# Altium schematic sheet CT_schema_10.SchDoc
size 209 x 185 mm
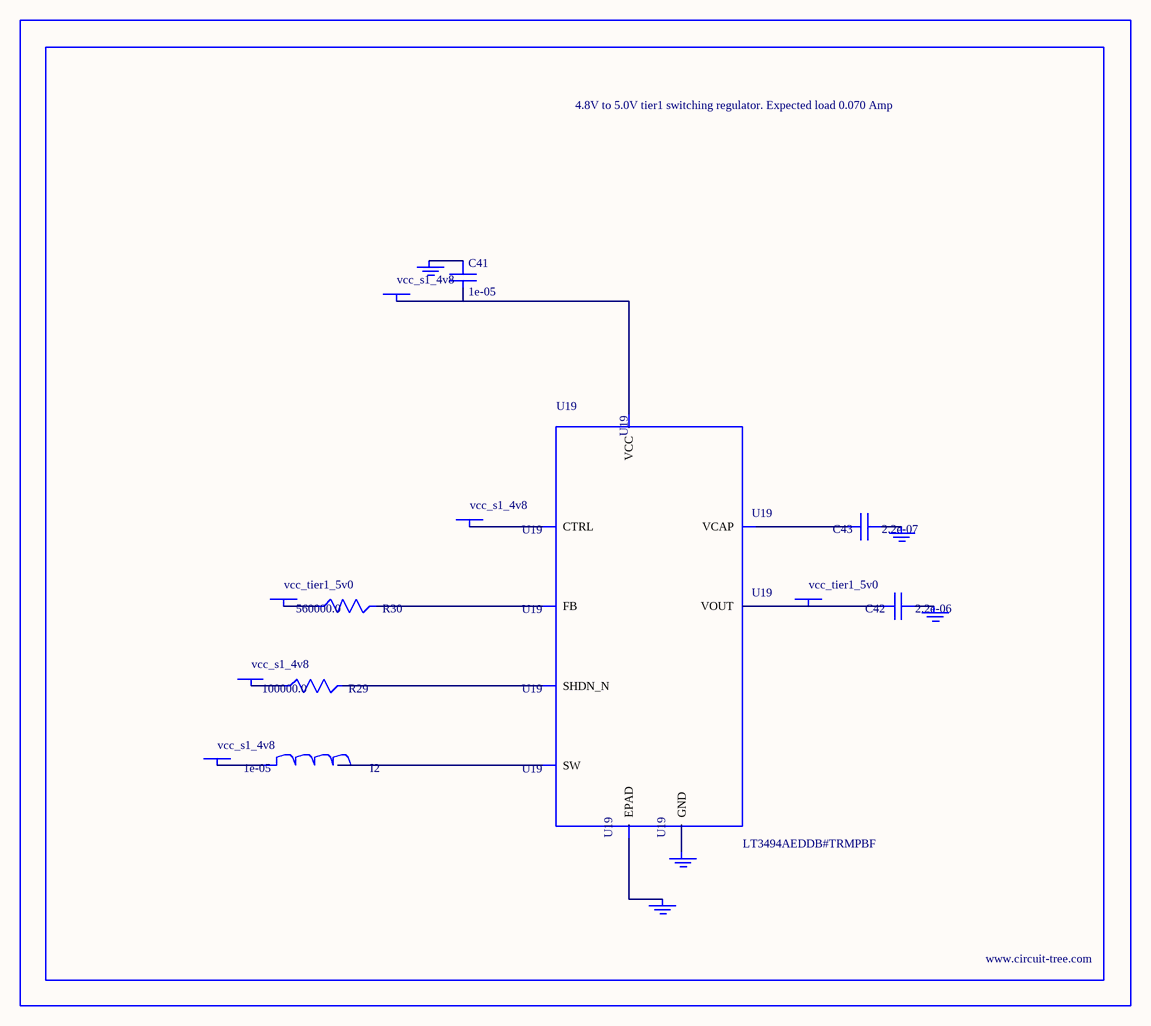
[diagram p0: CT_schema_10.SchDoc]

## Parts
BORDER9  (no value)
C41  1e-05  [C1210]
C42  2.2e-06  [C0603]
C43  2.2e-07  [C0603]
GND_INSTANCE_9_0  (no value)
GND_INSTANCE_9_1  (no value)
GND_INSTANCE_9_2  (no value)
GND_INSTANCE_9_3  (no value)
GND_INSTANCE_9_4  (no value)
I2  1e-05  [L1210]
POWER_INSTANCE_9_0  vcc_s1_4v8
POWER_INSTANCE_9_1  vcc_s1_4v8
POWER_INSTANCE_9_2  vcc_s1_4v8
POWER_INSTANCE_9_3  vcc_s1_4v8
POWER_INSTANCE_9_4  vcc_tier1_5v0
POWER_INSTANCE_9_5  vcc_tier1_5v0
R29  100000.0  [R0603]
R30  560000.0  [R0603]
U19  LT3494AEDDB#TRMPBF  [DFN-8_DDB]

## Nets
NetC41_1: C41.1 GND_INSTANCE_9_0.0(GND)
NetC41_2: C41.2 POWER_INSTANCE_9_1.0(PWR) U19.3(VCC)
NetC42_1: C42.1 GND_INSTANCE_9_1.0(GND)
NetC42_2: C42.2 POWER_INSTANCE_9_5.0(PWR) U19.7(VOUT)
NetC43_1: C43.1 GND_INSTANCE_9_2.0(GND)
NetC43_2: C43.2 U19.8(VCAP)
NetGND_INSTANCE_9_3_0: GND_INSTANCE_9_3.0(GND) U19.9(EPAD)
NetGND_INSTANCE_9_4_0: GND_INSTANCE_9_4.0(GND) U19.2(GND)
NetI2_1: I2.1 POWER_INSTANCE_9_0.0(PWR)
NetI2_2: I2.2 U19.1(SW)
NetPOWER_INSTANCE_9_2_0: POWER_INSTANCE_9_2.0(PWR) U19.4(CTRL)
NetPOWER_INSTANCE_9_3_0: POWER_INSTANCE_9_3.0(PWR) R29.1
NetPOWER_INSTANCE_9_4_0: POWER_INSTANCE_9_4.0(PWR) R30.1
NetR29_2: R29.2 U19.5(SHDN_N)
NetR30_2: R30.2 U19.6(FB)

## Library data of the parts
BORDER9 = BORDER_PAGE9
C41 = C1210C106K5PACTU
C42 = GRM188R61H225KE1115D
C43 = C0603C224K3RAC
GND_INSTANCE_9_0-GND_INSTANCE_9_4 = GND
I2 = CBC3225T100MR
POWER_INSTANCE_9_0-POWER_INSTANCE_9_5 = PWR
R29 = RC0603JR-07100KL
R30 = RC0603JR-07560KL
